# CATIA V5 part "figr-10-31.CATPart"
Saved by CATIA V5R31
Part number: Part1
Bounding box of the stored display mesh (mm): x -84 to 53, y -93.367 to 104.555, z -56.529 to 41.172
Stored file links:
  D:\PROJECTS\Project 2021\US EDITION\CATIA V5 6R 2021\Resources\Part Files\c10_catia_v5_6r2021_prt\c10_catia_v5_6r2021_prt\figr-10-31.CATPart
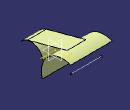
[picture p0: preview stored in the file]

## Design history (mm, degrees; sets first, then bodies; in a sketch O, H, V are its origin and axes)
Body1 (main body)
  Sketch1 on yz-plane, origin (0, 0, 0), H (0, 1, 0), V (0, 0, 1)
    arc A1 centre (-59.8904, -36.5447) radius 41.17 from (-93.3668, -12.5802) to (-23.896, -56.5291) cw
  Extrude1: Element1 Sketch1, Lim1 20, Lim2 42
  Sketch2 on yz-plane, origin (0, 0, 0), H (0, 1, 0), V (0, 0, 1)
    arc A1 centre (78.3128, -29.0048) radius 70.3421 from (104.5554, 36.2588) to (11.1367, -49.8706) ccw
  Extrude2: Element1 Sketch2, Lim1 53, Lim2 84
  Sketch3 on xy-plane, origin (0, 0, 0), H (1, 0, 0), V (0, 1, 0)
    line L1 (-58.0902, 93.9265) -> (40.4277, 93.9265)
    horizontal: L1 H
  Sweep1: type Segment, GuideSurf (Extrude1; Extrude2), Spine Sketch3, Length1 20, Length2 0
